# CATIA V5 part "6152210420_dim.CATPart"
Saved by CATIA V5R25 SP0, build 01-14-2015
Part number: 6152210420_dim
Source: made
Property "PROI_CREATED_ON": "12/17/2008 9:21:37 AM"
Property "BLANK_DRAWING": "--"
Property "DRAWN_BY": "ALG"
Property "FINISH": "--"
Property "HEAT_TREATMENT": "ASSIGN"
Property "MATERIAL": "ASSIGN"
Property "PROJECT": "--"
Property "PROTOTYPE_NO": "--"
Property "RELATED_DRAWING": "--"
Property "COMPLETE_MATERIAL": "ASSIGN-ASSIGN"
Property "DESCRIPTION": "Q-AUDIT 350"
Property "DRAWING_EXIST": "--"
Property "MANUFACTURER": "--"
Property "MANUFACTURER_2": "--"
Property "MANUFACTURER_REF": "--"
Property "TYPE_PART": "A"
Property "TODAY_DATE": "2021/12/06"
Property "PDMREV": "01.0"
Property "PDMRL": "Production"
Property "PROI_REVISION": "01"
Property "PROI_VERSION": "0"
Property "PROI_RELEASE": "Production"
Property "PTC_MODIFIED": false
Property "MFG_WP_MATERIAL": "ASSIGN"
Property "COMPANY_CODE": "---"
Property "DESCRIPTION_JP": "--"
Property "PQP_DOCUMENT": "--"
Property "SUPPLIER": "--"
Property "REFERENCE": "6152210420"
Property "PTC_WM_REVISION": "01"
Property "PTC_WM_ITERATION": "0"
Property "PTC_WM_VERSION": "01.0"
Property "PTC_WM_LIFECYCLE_STATE": "Production"
Property "PTC_WM_LIFECYCLE": "Design_Process"
Property "PTC_WM_LOCATION": "/Products/TORQUE MEASUREMENT SYSTEMS/A3020 - Q-AUDIT/9-01-Dimensional Drawings a"
Property "PTC_WM_CREATED_BY": "Alain Le Goc (grealg) (grealg: CPD)"
Property "PTC_WM_CREATED_ON": "06-Dec-21 03:49:56 PM"
Property "PTC_WM_MODIFIED_BY": "Alain Le Goc (grealg) (grealg: CPD)"
Property "PTC_WM_MODIFIED_ON": "06-Dec-21 03:58:45 PM"
Property "PTC_WM_TEAM": "Default"
Property "PTC_ORGANIZATION_ID": "CPD"
Property "EXPORT_CONTROL": "NULL"
Property "PTC_WM_NAME": "6152210420_dim.prt"
Property "PTC_WM_NUMBER": "6152210420_DIM.PRT"
Property "PTC_COMMON_NAME": "6152210420_dim.prt"
Property "PTC_MASTER_MATERIAL": "ASSIGN"
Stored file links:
  d:\ptc\Echange\temp\6152210420_dim.CATPart

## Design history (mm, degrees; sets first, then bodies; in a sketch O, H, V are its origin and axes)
AxisSystem1 "CS0": origin (0, 0, 0), X (1, 0, 0), Y (0, 1, 0), Z (0, 0, 1)
Set1
  DatumSurface1 "Sheet.1"
  DatumSurface2 "Sheet.2"
  DatumSurface3 "Sheet.3"
  DatumSurface4 "Sheet.4"
  DatumSurface5 "Sheet.5"
  DatumSurface6 "Sheet.6"
  DatumSurface7 "Sheet.7"
  DatumSurface8 "Sheet.8"
  DatumSurface9 "Sheet.9"
  DatumSurface10 "Sheet.10"
  DatumSurface11 "Sheet.11"
  DatumSurface12 "Sheet.12"
  DatumSurface13 "Sheet.13"
  DatumSurface14 "Sheet.14"
  DatumSurface15 "Sheet.15"
  DatumSurface16 "Sheet.16"
  DatumSurface17 "Sheet.17"
  DatumSurface18 "Sheet.18"
  DatumSurface19 "Sheet.19"
  DatumSurface20 "Sheet.20"
  DatumSurface21 "Sheet.21"
  DatumSurface22 "Sheet.22"
  DatumSurface23 "Sheet.23"
  DatumSurface24 "Sheet.24"
  DatumSurface25 "Sheet.25"
  DatumSurface26 "Sheet.26"
  DatumSurface27 "Sheet.27"
  DatumSurface28 "Sheet.28"
  DatumSurface29 "Sheet.29"
  DatumSurface30 "Sheet.30"
  DatumSurface31 "Sheet.31"
  DatumSurface32 "Sheet.32"
  DatumSurface33 "Sheet.33"
  DatumSurface34 "Sheet.34"
  DatumSurface35 "Sheet.35"
  DatumSurface36 "Sheet.36"
  DatumSurface37 "Sheet.37"
  DatumSurface38 "Sheet.38"
  Plane1 "RIGHT": stored without definition
  Plane2 "TOP": stored without definition
  Plane3 "FRONT": stored without definition
Body1 "PartBody" (main body)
